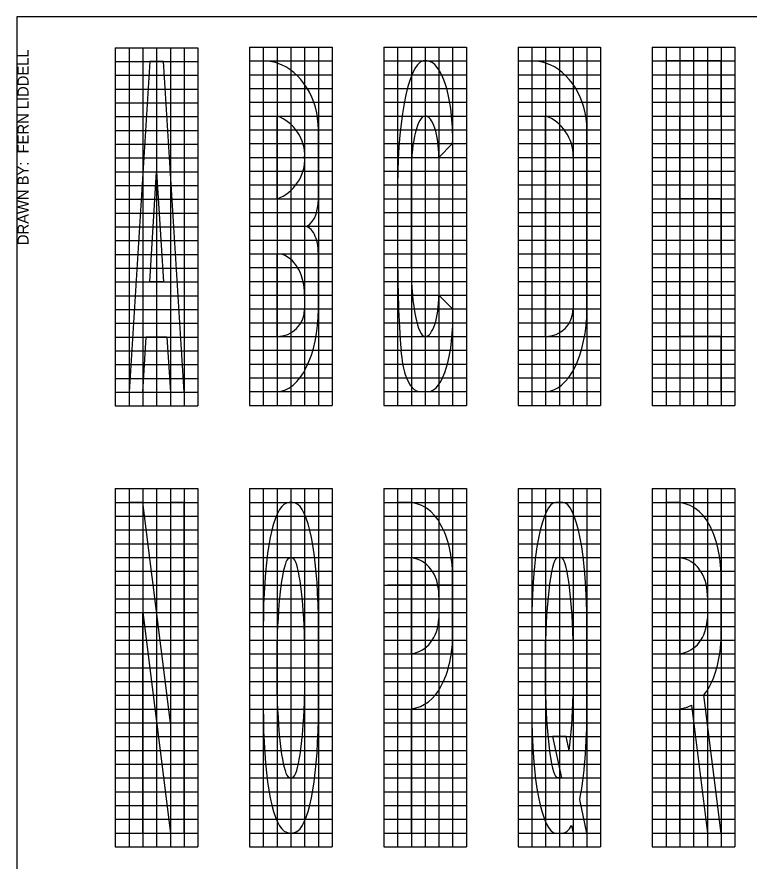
# Model space of a CAD drawing. Extents: x 99862 to 103151, y 100000 to 102076.
# Drawn here: x 99862 to 100926, y 100850 to 102076 of the extents above; entities that cross this region are included whole.
import ezdxf

# ---------------------------------------------------------------- set-up
doc = ezdxf.new("R2010")
doc.units = 0
for name, color, linetype in [('Level 1', 7, 'Continuous'), ('Level 15', 7, 'Continuous'), ('Level 4', 7, 'Continuous'), ('Level 62', 7, 'Continuous')]:
    doc.layers.add(name, color=color, linetype=linetype)

msp = doc.modelspace()

# ---------------------------------------------------------------- linework, layer by layer
at = {"layer": 'Level 1'}
msp.add_lwpolyline([(99862, 99999.5), (103151, 99999.5), (103151, 102075.5), (99862, 102075.5)], close=True, dxfattribs=at)
at = {"layer": 'Level 15'}
for p, q in [((100105, 101530.8), (100075, 102010.8)), ((100220, 102011.5), (100220, 101531.5)), ((100457.5, 102011.5), (100452.2, 102011.5)), ((100610, 102011.5), (100610, 101873.4)), ((100240, 101811.5), (100240, 101931.5)), ((100630, 101873.4), (100630, 101931.5)), ((100300, 101811.5), (100300, 101911.5)), ((100690, 101873.4), (100690, 101911.5)), ((100475, 101871.5), (100495, 101891.5)), ((100610, 101873.4), (100610, 101871.5)), ((100610, 101871.5), (100610, 101671.5)), ((100630, 101871.5), (100630, 101873.4)), ((100630, 101671.5), (100630, 101871.5)), ((100670.1, 101873.4), (100670, 101871.5)), ((100670, 101871.5), (100670, 101671.5)), ((100690, 101871.5), (100690, 101873.4)), ((100690, 101671.5), (100690, 101871.5)), ((100435, 101711.5), (100435, 101851.5)), ((100055, 101690.8), (100065, 101850.8)), ((100415, 101811.5), (100415, 101731.5)), ((100240, 101611.5), (100240, 101731.5)), ((100300, 101651.5), (100300, 101731.5)), ((100280, 101671.5), (100280, 101651.5)), ((100495, 101651.5), (100475, 101671.5)), ((100610, 101671.5), (100610, 101669)), ((100610, 101669), (100610, 101531.5)), ((100630, 101669), (100630, 101671.5)), ((100630, 101611.5), (100630, 101669)), ((100670, 101671.5), (100670, 101669)), ((100670, 101669), (100670, 101651.5)), ((100690, 101669), (100690, 101671.5)), ((100690, 101651.5), (100690, 101669)), ((100045, 101530.8), (100050, 101610.7)), ((100080, 101610.7), (100050, 101610.7)), ((100220, 101531.5), (100236.3, 101531.5)), ((100236.3, 101531.5), (100240, 101531.5)), ((100449.6, 101531.5), (100459.5, 101531.5)), ((100610, 101531.5), (100630, 101531.5)), ((100425, 101370.8), (100415, 101370.8)), ((100415, 101370.8), (100415, 100890.8)), ((100427.5, 101370.8), (100425, 101370.8)), ((100655, 101370.8), (100645.1, 101370.8)), ((100815, 101370.8), (100805, 101370.8)), ((100805, 101370.8), (100805, 100890.8)), ((100817.5, 101370.8), (100815, 101370.8)), ((100435, 101151.3), (100435, 101290.2)), ((100647.5, 101290.8), (100652.5, 101290.8)), ((100825, 101151.3), (100825, 101290.2)), ((100495, 101182.3), (100495, 101263.8)), ((100885, 101182.3), (100885, 101263.8)), ((100475, 101233.6), (100475, 101202.2)), ((100865, 101233.6), (100865, 101202.2)), ((100220, 101189.5), (100220, 101130.8)), ((100300, 101130.8), (100300, 101189.5)), ((100610, 101190.8), (100610, 101070.8)), ((100690, 101070.8), (100690, 101190.8)), ((100240, 101130.8), (100240, 101169.5)), ((100280, 101169.5), (100280, 101130.8)), ((100630, 101090.8), (100630, 101170.8)), ((100670, 101170.8), (100670, 101090.8)), ((100220, 101130.8), (100220, 101072)), ((100240, 101092), (100240, 101130.8)), ((100280, 101130.8), (100280, 101092)), ((100300, 101072), (100300, 101130.8)), ((100860, 101090.8), (100859.7, 101090.8)), ((100885, 100890.8), (100860, 101090.8)), ((100435, 100890.8), (100435, 101071.2)), ((100825, 100890.8), (100825, 101071.2)), ((100841.8, 101076.4), (100865, 100890.8)), ((100660, 101030.8), (100640, 101030.8)), ((100640, 101030.8), (100652.9, 100970.8)), ((100664.4, 101010.4), (100660, 101030.8)), ((100652.5, 100970.8), (100647.5, 100970.8)), ((100690, 100890.8), (100679.6, 100939.3)), ((100667.6, 100901.9), (100670, 100890.8)), ((100415, 100890.8), (100435, 100890.8)), ((100645.1, 100890.8), (100655, 100890.8)), ((100670, 100890.8), (100690, 100890.8)), ((100805, 100890.8), (100825, 100890.8)), ((100865, 100890.8), (100885, 100890.8))]:
    msp.add_line(p, q, dxfattribs=at)
for points in [[(100050, 101610.8), (100080, 101610.8), (100085, 101530.8), (100105, 101530.8), (100075, 102010.8), (100055, 102010.8), (100025, 101530.8), (100045, 101530.8)], [(100825, 101731.5), (100885, 101731.5), (100885, 101811.5), (100825, 101811.5), (100825, 101931.5), (100885, 101931.5), (100885, 102011.5), (100825, 102011.5), (100815, 102011.5), (100805, 102011.5), (100805, 101531.5), (100820, 101531.5), (100825, 101531.5), (100885, 101531.5), (100885, 101611.5), (100825, 101611.5)], [(100075, 101690.8), (100055, 101690.8), (100065, 101850.8)], [(100045, 101210.8), (100085, 100890.8), (100105, 100890.8), (100105, 101370.8), (100085, 101370.8), (100085, 101050.8), (100045, 101370.8), (100025, 101370.8), (100025, 100890.8), (100045, 100890.8)]]:
    msp.add_lwpolyline(points, close=True, dxfattribs=at)
for centre in [(100240, 101651.5), (100630, 101651.5)]:
    msp.add_arc(centre, 40, 270, 0, dxfattribs=at)
for centre, major_axis, ratio, start_param, end_param in [((100220, 101911.5), (0, -100), 0.8, 2.888912, 3.141593), ((100455.7, 101819.6), (1.9, -192.1), 0.212259, 3.181472, 4.752268), ((100454.9, 101892.1), (-2.7, -119.4), 0.33574, 1.572843, 3.14364), ((100610, 101911.5), (0, -100), 0.8, 2.888912, 3.141593), ((100220, 101911.5), (0, -100), 0.8, 1.570796, 2.888912), ((100610, 101911.5), (0, -100), 0.8, 1.570796, 2.888912), ((100236.5, 101885.8), (28.3, -42.4), 0.784465, 0.785398, 2.356194), ((100455, 101851.5), (0, -80), 0.25, 3.141593, 4.712389), ((100455, 101871.5), (0, -60), 0.333333, 1.570796, 3.141593), ((100626.5, 101885.8), (28.3, -42.4), 0.784465, 0.826187, 2.356194), ((100236.5, 101857.2), (-28.3, -42.4), 0.784465, 0.785398, 2.356194), ((100280, 101811.5), (0, -40), 0.5, 0, 1.570796), ((100280, 101731.5), (0, -40), 0.5, 1.570796, 3.141593), ((100240, 101671.5), (0, -60), 0.666667, 1.570796, 3.141593), ((100520.5, 101826.5), (-23.4, -472.4), 0.217682, 4.925669, 5.24381), ((100455, 101711.5), (0, -100), 0.2, 4.712389, 6.283185), ((100455, 101671.5), (0, -60), 0.333333, 6.283185, 7.853982), ((100240, 101651.5), (0, -120), 0.5, 0, 1.570796), ((100455.5, 101650.4), (4.1, -118.9), 0.332625, 6.280854, 7.85165), ((100630, 101651.5), (0, -120), 0.5, 0, 1.570796), ((100443.5, 101651.6), (-7.6, -107.5), 0.217694, 5.320592, 5.812457), ((100496.9, 101774.9), (-51.4, -243.1), 0.245192, 5.877502, 6.350549), ((100260, 101170.4), (5, -199.2), 0.199299, 3.270146, 4.611011), ((100250, 100950), (-10.5, -420.8), 0.199299, 3.026472, 3.266466), ((100260, 101170.4), (-5, -199.1), 0.199299, 1.671694, 3.012648), ((100428.5, 101306.6), (0, -64.2), 0.883106, 2.078693, 3.158066), ((100650, 101171.7), (5, -199.1), 0.199299, 3.141308, 4.611491), ((100650, 101171.6), (-5, -199.2), 0.199299, 1.672174, 3.141673), ((100818.5, 101306.6), (0, -64.2), 0.883106, 2.078693, 3.158066), ((100447.5, 101262.4), (0, -98.2), 0.483719, 1.584917, 2.445445), ((100837.5, 101262.4), (0, -98.2), 0.483719, 1.584917, 2.445445), ((100254.7, 101169.2), (-2.8, -120.3), 0.12203, 3.268534, 4.712481), ((100252.1, 100943.3), (-8.1, -347.1), 0.12203, 3.042542, 3.248083), ((100265.3, 101169.2), (2.8, -120.3), 0.12203, 1.570704, 3.018848), ((100427.7, 101258.9), (40.2, 0), 0.792657, 0.505828, 1.38755), ((100644.7, 101170.4), (-2.8, -120.3), 0.12203, 3.141685, 4.712481), ((100655.3, 101170.4), (2.8, -120.3), 0.12203, 1.570704, 3.1415), ((100817.7, 101258.9), (40.2, 0), 0.792657, 0.505828, 1.38755), ((100441.1, 101236.6), (0, -49.1), 0.691027, 1.570796, 2.445559), ((100831.1, 101236.6), (0, -49.1), 0.691027, 1.570796, 2.445559), ((100441.1, 101236.6), (0, -49.1), 0.691027, 1.529951, 1.570796), ((100441.1, 101234.5), (3.1, -48.9), 0.691023, 1.508615, 1.52981), ((100831.1, 101236.6), (0, -49.1), 0.691027, 1.529951, 1.570796), ((100831.1, 101234.5), (3.1, -48.9), 0.691023, 1.508615, 1.52981), ((100441.3, 101204.8), (-0.1, -48.9), 0.690438, 0.696034, 1.518966), ((100831.3, 101204.8), (-0.1, -48.9), 0.690438, 0.696034, 1.518966), ((100447.5, 101179), (0, -98.3), 0.483307, 0.696034, 1.604189), ((100837.5, 101179), (0, -98.3), 0.483307, 0.696034, 1.604189), ((100427.7, 101182.6), (40.2, 0), 0.793333, 4.895635, 5.777357), ((100817.7, 101182.6), (40.2, 0), 0.793333, 4.895635, 5.777357), ((100428.8, 101134.5), (0, -63.8), 0.882353, 0.111341, 1.064968), ((100818.8, 101134.5), (0, -63.7), 0.882353, 0.814442, 1.064968), ((100254.7, 101092.3), (2.8, -120.3), 0.12203, 4.712297, 6.156244), ((100265.3, 101092.3), (-2.8, -120.3), 0.12203, 0.122745, 1.570889), ((100644.7, 101091.1), (2.8, -120.3), 0.12203, 4.712297, 6.283093), ((100655.3, 101091.1), (-2.8, -120.3), 0.12203, 0.838784, 1.570889), ((100260, 101091.2), (-5, -199.2), 0.199299, 4.813767, 6.154632), ((100260, 101091.1), (5, -199.1), 0.199299, 0.128945, 1.469898), ((100650, 101089.9), (-5, -199.2), 0.199299, 4.813767, 6.283266), ((100650, 101089.8), (5, -199.1), 0.199299, 0.708406, 1.469898), ((100818.8, 101134.5), (0, -63.8), 0.882353, 0.111341, 0.422215), ((100252.1, 101318.2), (8.1, -347.1), 0.12203, 6.176695, 6.382236), ((100655.3, 101091.1), (-2.8, -120.3), 0.12203, 0.000092, 0.023634), ((100650, 101089.8), (5, -199.1), 0.199299, 6.282901, 6.614442), ((100250, 101311.5), (10.5, -420.8), 0.199299, 6.158312, 6.398306)]:
    msp.add_ellipse(centre, major_axis=major_axis, ratio=ratio, start_param=start_param, end_param=end_param, dxfattribs=at)
at = {"layer": 'Level 4'}
for p, q in [((100005, 102030.8), (100005, 101510.8)), ((100005, 102030.8), (100125, 102030.8)), ((100025, 102030.8), (100025, 101510.8)), ((100045, 102030.8), (100045, 101510.8)), ((100065, 102030.8), (100065, 101510.8)), ((100085, 102030.8), (100085, 101510.8)), ((100105, 102030.8), (100105, 101510.8)), ((100125, 102030.8), (100125, 101510.8)), ((100200, 102031.5), (100200, 101511.5)), ((100200, 102031.5), (100320, 102031.5)), ((100220, 102031.5), (100220, 101511.5)), ((100240, 102031.5), (100240, 101511.5)), ((100260, 102031.5), (100260, 101511.5)), ((100280, 102031.5), (100280, 101511.5)), ((100300, 102031.5), (100300, 101511.5)), ((100320, 102031.5), (100320, 101511.5)), ((100395, 102031.5), (100395, 101511.5)), ((100395, 102031.5), (100515, 102031.5)), ((100415, 102031.5), (100415, 101511.5)), ((100435, 102031.5), (100435, 101511.5)), ((100455, 102031.5), (100455, 101511.5)), ((100475, 102031.5), (100475, 101511.5)), ((100495, 102031.5), (100495, 101511.5)), ((100515, 102031.5), (100515, 101511.5)), ((100590, 102031.5), (100590, 101511.5)), ((100590, 102031.5), (100710, 102031.5)), ((100610, 102031.5), (100610, 101511.5)), ((100630, 102031.5), (100630, 101511.5)), ((100650, 102031.5), (100650, 101511.5)), ((100670, 102031.5), (100670, 101511.5)), ((100690, 102031.5), (100690, 101511.5)), ((100710, 102031.5), (100710, 101511.5)), ((100785, 102031.5), (100785, 101511.5)), ((100785, 102031.5), (100905, 102031.5)), ((100805, 102031.5), (100805, 101511.5)), ((100825, 102031.5), (100825, 101511.5)), ((100845, 102031.5), (100845, 101511.5)), ((100865, 102031.5), (100865, 101511.5)), ((100885, 102031.5), (100885, 101511.5)), ((100905, 102031.5), (100905, 101511.5)), ((100005, 102010.8), (100125, 102010.8)), ((100200, 102011.5), (100320, 102011.5)), ((100395, 102011.5), (100515, 102011.5)), ((100590, 102011.5), (100710, 102011.5)), ((100785, 102011.5), (100905, 102011.5)), ((100005, 101990.8), (100125, 101990.8)), ((100200, 101991.5), (100320, 101991.5)), ((100395, 101991.5), (100515, 101991.5)), ((100590, 101991.5), (100710, 101991.5)), ((100785, 101991.5), (100905, 101991.5)), ((100005, 101970.8), (100125, 101970.8)), ((100200, 101971.5), (100320, 101971.5)), ((100395, 101971.5), (100515, 101971.5)), ((100590, 101971.5), (100710, 101971.5)), ((100785, 101971.5), (100905, 101971.5)), ((100005, 101950.8), (100125, 101950.8)), ((100200, 101951.5), (100320, 101951.5)), ((100395, 101951.5), (100515, 101951.5)), ((100590, 101951.5), (100710, 101951.5)), ((100785, 101951.5), (100905, 101951.5)), ((100005, 101930.8), (100125, 101930.8)), ((100200, 101931.5), (100320, 101931.5)), ((100395, 101931.5), (100515, 101931.5)), ((100590, 101931.5), (100710, 101931.5)), ((100785, 101931.5), (100905, 101931.5)), ((100005, 101910.8), (100125, 101910.8)), ((100200, 101911.5), (100320, 101911.5)), ((100395, 101911.5), (100515, 101911.5)), ((100590, 101911.5), (100710, 101911.5)), ((100785, 101911.5), (100905, 101911.5)), ((100005, 101890.8), (100125, 101890.8)), ((100200, 101891.5), (100320, 101891.5)), ((100395, 101891.5), (100515, 101891.5)), ((100590, 101891.5), (100710, 101891.5)), ((100785, 101891.5), (100905, 101891.5)), ((100005, 101870.8), (100125, 101870.8)), ((100200, 101871.5), (100320, 101871.5)), ((100395, 101871.5), (100515, 101871.5)), ((100590, 101871.5), (100710, 101871.5)), ((100785, 101871.5), (100905, 101871.5)), ((100200, 101851.5), (100320, 101851.5)), ((100395, 101851.5), (100515, 101851.5)), ((100590, 101851.5), (100710, 101851.5)), ((100785, 101851.5), (100905, 101851.5)), ((100005, 101850.8), (100125, 101850.8)), ((100005, 101830.8), (100125, 101830.8)), ((100200, 101831.5), (100320, 101831.5)), ((100395, 101831.5), (100515, 101831.5)), ((100590, 101831.5), (100710, 101831.5)), ((100785, 101831.5), (100905, 101831.5)), ((100005, 101810.8), (100125, 101810.8)), ((100200, 101811.5), (100320, 101811.5)), ((100395, 101811.5), (100515, 101811.5)), ((100590, 101811.5), (100710, 101811.5)), ((100785, 101811.5), (100905, 101811.5)), ((100005, 101790.8), (100125, 101790.8)), ((100200, 101791.5), (100320, 101791.5)), ((100395, 101791.5), (100515, 101791.5)), ((100590, 101791.5), (100710, 101791.5)), ((100785, 101791.5), (100905, 101791.5)), ((100005, 101770.8), (100125, 101770.8)), ((100200, 101771.5), (100320, 101771.5)), ((100395, 101771.5), (100515, 101771.5)), ((100590, 101771.5), (100710, 101771.5)), ((100785, 101771.5), (100905, 101771.5)), ((100005, 101750.8), (100125, 101750.8)), ((100200, 101751.5), (100320, 101751.5)), ((100395, 101751.5), (100515, 101751.5)), ((100590, 101751.5), (100710, 101751.5)), ((100785, 101751.5), (100905, 101751.5)), ((100005, 101730.8), (100125, 101730.8)), ((100200, 101731.5), (100320, 101731.5)), ((100395, 101731.5), (100515, 101731.5)), ((100590, 101731.5), (100710, 101731.5)), ((100785, 101731.5), (100905, 101731.5)), ((100005, 101710.8), (100125, 101710.8)), ((100200, 101711.5), (100320, 101711.5)), ((100395, 101711.5), (100515, 101711.5)), ((100590, 101711.5), (100710, 101711.5)), ((100785, 101711.5), (100905, 101711.5)), ((100005, 101690.8), (100125, 101690.8)), ((100200, 101691.5), (100320, 101691.5)), ((100395, 101691.5), (100515, 101691.5)), ((100590, 101691.5), (100710, 101691.5)), ((100785, 101691.5), (100905, 101691.5)), ((100005, 101670.8), (100125, 101670.8)), ((100200, 101671.5), (100320, 101671.5)), ((100395, 101671.5), (100515, 101671.5)), ((100590, 101671.5), (100710, 101671.5)), ((100785, 101671.5), (100905, 101671.5)), ((100005, 101650.8), (100125, 101650.8)), ((100200, 101651.5), (100320, 101651.5)), ((100395, 101651.5), (100515, 101651.5)), ((100590, 101651.5), (100710, 101651.5)), ((100785, 101651.5), (100905, 101651.5)), ((100005, 101630.8), (100125, 101630.8)), ((100200, 101631.5), (100320, 101631.5)), ((100395, 101631.5), (100515, 101631.5)), ((100590, 101631.5), (100710, 101631.5)), ((100785, 101631.5), (100905, 101631.5)), ((100005, 101610.8), (100125, 101610.8)), ((100200, 101611.5), (100320, 101611.5)), ((100395, 101611.5), (100515, 101611.5)), ((100590, 101611.5), (100710, 101611.5)), ((100785, 101611.5), (100905, 101611.5)), ((100005, 101590.8), (100125, 101590.8)), ((100200, 101591.5), (100320, 101591.5)), ((100395, 101591.5), (100515, 101591.5)), ((100590, 101591.5), (100710, 101591.5)), ((100785, 101591.5), (100905, 101591.5)), ((100005, 101570.8), (100125, 101570.8)), ((100200, 101571.5), (100320, 101571.5)), ((100395, 101571.5), (100515, 101571.5)), ((100590, 101571.5), (100710, 101571.5)), ((100785, 101571.5), (100905, 101571.5)), ((100005, 101550.8), (100125, 101550.8)), ((100200, 101551.5), (100320, 101551.5)), ((100395, 101551.5), (100515, 101551.5)), ((100590, 101551.5), (100710, 101551.5)), ((100785, 101551.5), (100905, 101551.5)), ((100005, 101530.8), (100125, 101530.8)), ((100200, 101531.5), (100320, 101531.5)), ((100395, 101531.5), (100515, 101531.5)), ((100590, 101531.5), (100710, 101531.5)), ((100785, 101531.5), (100905, 101531.5)), ((100005, 101510.8), (100125, 101510.8)), ((100005, 101510.8), (100125, 101510.8)), ((100200, 101511.5), (100320, 101511.5)), ((100395, 101511.5), (100515, 101511.5)), ((100590, 101511.5), (100710, 101511.5)), ((100785, 101511.5), (100905, 101511.5)), ((100005, 101390.8), (100005, 100870.8)), ((100005, 101390.8), (100125, 101390.8)), ((100025, 101390.8), (100025, 100870.8)), ((100045, 101390.8), (100045, 100870.8)), ((100065, 101390.8), (100065, 100870.8)), ((100085, 101390.8), (100085, 100870.8)), ((100105, 101390.8), (100105, 100870.8)), ((100125, 101390.8), (100125, 100870.8)), ((100200, 101390.8), (100200, 100870.8)), ((100200, 101390.8), (100320, 101390.8)), ((100220, 101390.8), (100220, 100870.8)), ((100240, 101390.8), (100240, 100870.8)), ((100260, 101390.8), (100260, 100870.8)), ((100280, 101390.8), (100280, 100870.8)), ((100300, 101390.8), (100300, 100870.8)), ((100320, 101390.8), (100320, 100870.8)), ((100395, 101390.8), (100395, 100870.8)), ((100395, 101390.8), (100515, 101390.8)), ((100415, 101390.8), (100415, 100870.8)), ((100435, 101390.8), (100435, 100870.8)), ((100455, 101390.8), (100455, 100870.8)), ((100475, 101390.8), (100475, 100870.8)), ((100495, 101390.8), (100495, 100870.8)), ((100515, 101390.8), (100515, 100870.8)), ((100590, 101390.8), (100590, 100870.8)), ((100590, 101390.8), (100710, 101390.8)), ((100610, 101390.8), (100610, 100870.8)), ((100630, 101390.8), (100630, 100870.8)), ((100650, 101390.8), (100650, 100870.8)), ((100670, 101390.8), (100670, 100870.8)), ((100690, 101390.8), (100690, 100870.8)), ((100710, 101390.8), (100710, 100870.8)), ((100785, 101390.8), (100785, 100870.8)), ((100785, 101390.8), (100905, 101390.8)), ((100805, 101390.8), (100805, 100870.8)), ((100825, 101390.8), (100825, 100870.8)), ((100845, 101390.8), (100845, 100870.8)), ((100865, 101390.8), (100865, 100870.8)), ((100885, 101390.8), (100885, 100870.8)), ((100905, 101390.8), (100905, 100870.8)), ((100005, 101370.8), (100125, 101370.8)), ((100200, 101370.8), (100320, 101370.8)), ((100395, 101370.8), (100515, 101370.8)), ((100590, 101370.8), (100710, 101370.8)), ((100785, 101370.8), (100905, 101370.8)), ((100005, 101350.8), (100125, 101350.8)), ((100200, 101350.8), (100320, 101350.8)), ((100395, 101350.8), (100515, 101350.8)), ((100590, 101350.8), (100710, 101350.8)), ((100785, 101350.8), (100905, 101350.8)), ((100005, 101330.8), (100125, 101330.8)), ((100200, 101330.8), (100320, 101330.8)), ((100395, 101330.8), (100515, 101330.8)), ((100590, 101330.8), (100710, 101330.8)), ((100785, 101330.8), (100905, 101330.8)), ((100005, 101310.8), (100125, 101310.8)), ((100200, 101310.8), (100320, 101310.8)), ((100395, 101310.8), (100515, 101310.8)), ((100590, 101310.8), (100710, 101310.8)), ((100785, 101310.8), (100905, 101310.8)), ((100005, 101290.8), (100125, 101290.8)), ((100200, 101290.8), (100320, 101290.8)), ((100395, 101290.8), (100515, 101290.8)), ((100590, 101290.8), (100710, 101290.8)), ((100785, 101290.8), (100905, 101290.8)), ((100005, 101270.8), (100125, 101270.8)), ((100200, 101270.8), (100320, 101270.8)), ((100395, 101270.8), (100515, 101270.8)), ((100590, 101270.8), (100710, 101270.8)), ((100785, 101270.8), (100905, 101270.8)), ((100005, 101250.8), (100125, 101250.8)), ((100200, 101250.8), (100320, 101250.8)), ((100395, 101250.8), (100515, 101250.8)), ((100494.7, 101250.8), (100400.4, 101250.8)), ((100590, 101250.8), (100710, 101250.8)), ((100785, 101250.8), (100905, 101250.8)), ((100005, 101230.8), (100125, 101230.8)), ((100200, 101230.8), (100320, 101230.8)), ((100395, 101230.8), (100515, 101230.8)), ((100590, 101230.8), (100710, 101230.8)), ((100785, 101230.8), (100905, 101230.8)), ((100005, 101210.8), (100125, 101210.8)), ((100200, 101210.8), (100320, 101210.8)), ((100395, 101210.8), (100515, 101210.8)), ((100590, 101210.8), (100710, 101210.8)), ((100785, 101210.8), (100905, 101210.8)), ((100005, 101190.8), (100125, 101190.8)), ((100200, 101190.8), (100320, 101190.8)), ((100395, 101190.8), (100515, 101190.8)), ((100590, 101190.8), (100710, 101190.8)), ((100785, 101190.8), (100905, 101190.8)), ((100005, 101170.8), (100125, 101170.8)), ((100200, 101170.8), (100320, 101170.8)), ((100395, 101170.8), (100515, 101170.8)), ((100590, 101170.8), (100710, 101170.8)), ((100785, 101170.8), (100905, 101170.8)), ((100005, 101150.8), (100125, 101150.8)), ((100200, 101150.8), (100320, 101150.8)), ((100395, 101150.8), (100515, 101150.8)), ((100590, 101150.8), (100710, 101150.8)), ((100785, 101150.8), (100905, 101150.8)), ((100005, 101130.8), (100125, 101130.8)), ((100200, 101130.8), (100320, 101130.8)), ((100395, 101130.8), (100515, 101130.8)), ((100590, 101130.8), (100710, 101130.8)), ((100785, 101130.8), (100905, 101130.8)), ((100005, 101110.8), (100125, 101110.8)), ((100200, 101110.8), (100320, 101110.8)), ((100395, 101110.8), (100515, 101110.8)), ((100590, 101110.8), (100710, 101110.8)), ((100785, 101110.8), (100905, 101110.8)), ((100005, 101090.8), (100125, 101090.8)), ((100200, 101090.8), (100320, 101090.8)), ((100395, 101090.8), (100515, 101090.8)), ((100590, 101090.8), (100710, 101090.8)), ((100785, 101090.8), (100905, 101090.8)), ((100005, 101070.8), (100125, 101070.8)), ((100200, 101070.8), (100320, 101070.8)), ((100395, 101070.8), (100515, 101070.8)), ((100590, 101070.8), (100710, 101070.8)), ((100785, 101070.8), (100905, 101070.8)), ((100005, 101050.8), (100125, 101050.8)), ((100200, 101050.8), (100320, 101050.8)), ((100395, 101050.8), (100515, 101050.8)), ((100590, 101050.8), (100710, 101050.8)), ((100785, 101050.8), (100905, 101050.8)), ((100005, 101030.8), (100125, 101030.8)), ((100200, 101030.8), (100320, 101030.8)), ((100395, 101030.8), (100515, 101030.8)), ((100590, 101030.8), (100710, 101030.8)), ((100785, 101030.8), (100905, 101030.8)), ((100005, 101010.8), (100125, 101010.8)), ((100200, 101010.8), (100320, 101010.8)), ((100395, 101010.8), (100515, 101010.8)), ((100590, 101010.8), (100710, 101010.8)), ((100785, 101010.8), (100905, 101010.8)), ((100005, 100990.8), (100125, 100990.8)), ((100200, 100990.8), (100320, 100990.8)), ((100395, 100990.8), (100515, 100990.8)), ((100590, 100990.8), (100710, 100990.8)), ((100785, 100990.8), (100905, 100990.8)), ((100005, 100970.8), (100125, 100970.8)), ((100200, 100970.8), (100320, 100970.8)), ((100395, 100970.8), (100515, 100970.8)), ((100590, 100970.8), (100710, 100970.8)), ((100785, 100970.8), (100905, 100970.8)), ((100005, 100950.8), (100125, 100950.8)), ((100200, 100950.8), (100320, 100950.8)), ((100395, 100950.8), (100515, 100950.8)), ((100590, 100950.8), (100710, 100950.8)), ((100785, 100950.8), (100905, 100950.8)), ((100005, 100930.8), (100125, 100930.8)), ((100200, 100930.8), (100320, 100930.8)), ((100395, 100930.8), (100515, 100930.8)), ((100590, 100930.8), (100710, 100930.8)), ((100785, 100930.8), (100905, 100930.8)), ((100005, 100910.8), (100125, 100910.8)), ((100200, 100910.8), (100320, 100910.8)), ((100395, 100910.8), (100515, 100910.8)), ((100590, 100910.8), (100710, 100910.8)), ((100785, 100910.8), (100905, 100910.8)), ((100005, 100890.8), (100125, 100890.8)), ((100200, 100890.8), (100320, 100890.8)), ((100395, 100890.8), (100515, 100890.8)), ((100590, 100890.8), (100710, 100890.8)), ((100785, 100890.8), (100905, 100890.8)), ((100005, 100870.8), (100125, 100870.8)), ((100200, 100870.8), (100320, 100870.8)), ((100395, 100870.8), (100515, 100870.8)), ((100590, 100870.8), (100710, 100870.8)), ((100785, 100870.8), (100905, 100870.8))]:
    msp.add_line(p, q, dxfattribs=at)

# ---------------------------------------------------------------- texts
at = {"layer": 'Level 62'}
msp.add_text('DRAWN BY:  FERN LIDDELL', height=16, rotation=90, dxfattribs=at).set_placement((99879, 101744.2))

doc.saveas('drawing.dxf')
